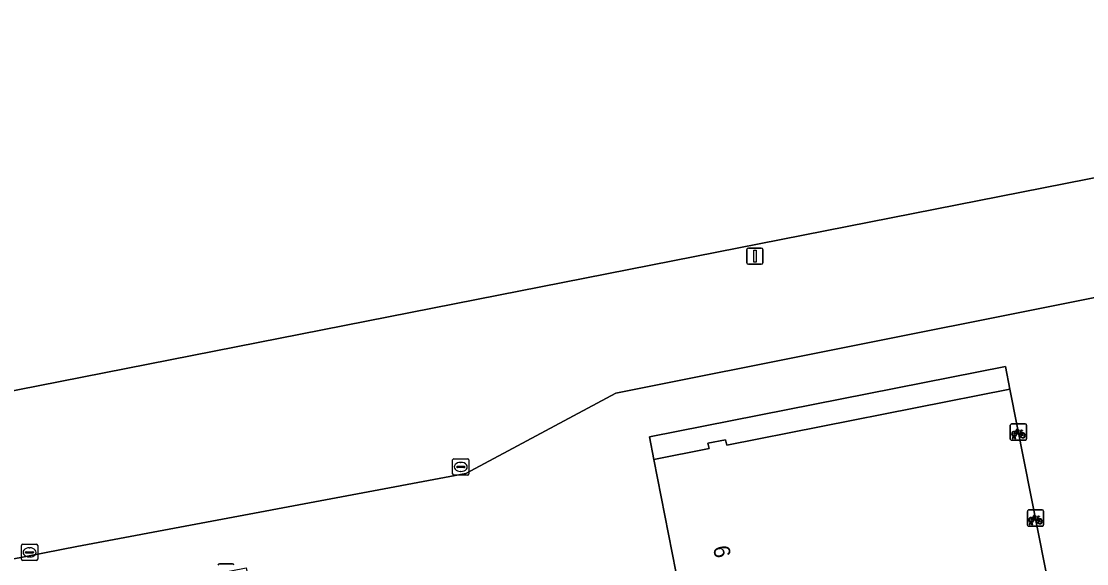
# Model space of a CAD drawing. Extents: x 160203 to 161530, y 379528 to 381797.
# Drawn here: x 160871 to 160936.5, y 380343.8 to 380377.1 of the extents above; entities that cross this region are included whole.
import ezdxf

# ---------------------------------------------------------------- set-up
doc = ezdxf.new("R2010")
doc.units = 0
for name, color, linetype in [('IMGEO_Fietsenrek', 7, 'Continuous'), ('IMGEO_Groenvoorziening', 7, 'Continuous'), ('IMGEO_Kolk', 7, 'Continuous'), ('IMGEO_Lichtmast', 7, 'Continuous'), ('IMGEO_Pand', 7, 'Continuous'), ('IMGEO_Pand_nummerreeks', 7, 'Continuous'), ('IMGEO_Voetpad_open', 7, 'Continuous')]:
    doc.layers.add(name, color=color, linetype=linetype)

msp = doc.modelspace()

# ---------------------------------------------------------------- linework, layer by layer
at = {"layer": 'IMGEO_Fietsenrek'}
for p, q in [((160931.819, 380351.461), (160931.819, 380352.302)), ((160931.819, 380352.302), (160931.819, 380351.461)), ((160931.894, 380352.386), (160932.735, 380352.386)), ((160932.735, 380352.386), (160931.894, 380352.386)), ((160932.819, 380352.311), (160932.819, 380351.47)), ((160932.819, 380351.47), (160932.819, 380352.311)), ((160932.744, 380351.386), (160931.903, 380351.386)), ((160931.903, 380351.386), (160932.744, 380351.386)), ((160931.946, 380351.47), (160931.985, 380351.63)), ((160931.98, 380351.47), (160931.946, 380351.47)), ((160932.015, 380351.618), (160931.98, 380351.47)), ((160932.057, 380351.642), (160932.056, 380351.646)), ((160932.098, 380351.47), (160932.064, 380351.612)), ((160932.088, 380351.653), (160932.089, 380351.646)), ((160932.096, 380351.616), (160932.131, 380351.47)), ((160932.131, 380351.47), (160932.098, 380351.47)), ((160932.506, 380351.935), (160932.542, 380351.84)), ((160932.866, 380346.175), (160932.866, 380347.016)), ((160932.866, 380347.016), (160932.866, 380346.175)), ((160932.941, 380347.1), (160933.782, 380347.1)), ((160933.782, 380347.1), (160932.941, 380347.1)), ((160933.866, 380347.025), (160933.866, 380346.184)), ((160933.866, 380346.184), (160933.866, 380347.025)), ((160932.993, 380346.184), (160933.032, 380346.344)), ((160933.027, 380346.184), (160932.993, 380346.184)), ((160933.062, 380346.332), (160933.027, 380346.184)), ((160933.104, 380346.356), (160933.103, 380346.36)), ((160933.145, 380346.184), (160933.111, 380346.326)), ((160933.135, 380346.367), (160933.136, 380346.36)), ((160933.143, 380346.33), (160933.178, 380346.184)), ((160933.178, 380346.184), (160933.145, 380346.184)), ((160933.553, 380346.649), (160933.589, 380346.554)), ((160933.791, 380346.1), (160932.95, 380346.1)), ((160932.95, 380346.1), (160933.791, 380346.1))]:
    msp.add_line(p, q, dxfattribs=at)
for points in [[(160932.132, 380351.912), (160932.227, 380352.076), (160932.313, 380352.062), (160932.315, 380352.053), (160932.259, 380352.042), (160932.232, 380351.997), (160932.488, 380351.956)], [(160932.488, 380351.956), (160932.513, 380352.005), (160932.507, 380352.009), (160932.484, 380352.013), (160932.472, 380352.02), (160932.471, 380352.023), (160932.473, 380352.028), (160932.568, 380352.013), (160932.57, 380352.003), (160932.56, 380351.99), (160932.548, 380351.984), (160932.534, 380351.99), (160932.506, 380351.935)], [(160932.153, 380351.86), (160932.101, 380351.77), (160932.061, 380351.745), (160932.062, 380351.792), (160932.117, 380351.886)], [(160932.428, 380351.668), (160932.378, 380351.668), (160932.187, 380351.919), (160932.168, 380351.887)], [(160932.475, 380351.931), (160932.218, 380351.972), (160932.201, 380351.943), (160932.368, 380351.723), (160932.475, 380351.931)], [(160932.523, 380351.833), (160932.493, 380351.91), (160932.384, 380351.692), (160932.427, 380351.692)], [(160932.457, 380351.692), (160932.577, 380351.691), (160932.533, 380351.805)], [(160932.553, 380351.812), (160932.608, 380351.667), (160932.458, 380351.667)], [(160933.179, 380346.626), (160933.274, 380346.79), (160933.36, 380346.776), (160933.362, 380346.767), (160933.306, 380346.756), (160933.279, 380346.711), (160933.535, 380346.67)], [(160933.2, 380346.574), (160933.148, 380346.484), (160933.108, 380346.459), (160933.109, 380346.506), (160933.164, 380346.6)], [(160933.475, 380346.382), (160933.425, 380346.382), (160933.234, 380346.633), (160933.215, 380346.601)], [(160933.522, 380346.645), (160933.265, 380346.686), (160933.248, 380346.657), (160933.415, 380346.437), (160933.522, 380346.645)], [(160933.57, 380346.547), (160933.54, 380346.624), (160933.431, 380346.406), (160933.474, 380346.406)], [(160933.504, 380346.406), (160933.624, 380346.405), (160933.58, 380346.519)], [(160933.6, 380346.526), (160933.655, 380346.381), (160933.505, 380346.381)], [(160933.535, 380346.67), (160933.56, 380346.719), (160933.554, 380346.723), (160933.531, 380346.727), (160933.519, 380346.734), (160933.518, 380346.737), (160933.52, 380346.742), (160933.615, 380346.727), (160933.617, 380346.717), (160933.607, 380346.704), (160933.595, 380346.698), (160933.581, 380346.704), (160933.553, 380346.649)]]:
    msp.add_lwpolyline(points, dxfattribs=at)
for centre, radius, start, end in [((160931.897, 380352.308), 0.0779, 92.4484, 184.28452), ((160931.897, 380352.308), 0.0779, 92.4484, 184.28452), ((160932.741, 380352.308), 0.0779, 2.4484, 94.28452), ((160932.741, 380352.308), 0.0779, 2.4484, 94.28452), ((160931.897, 380351.464), 0.0779, 182.4484, 274.28452), ((160931.897, 380351.464), 0.0779, 182.4484, 274.28452), ((160932.059, 380351.771), 0.159, 62.67661, 242.13685), ((160932.059, 380351.771), 0.129, 63.31916, 238.90302), ((160932.039, 380351.642), 0.0499, 12.8025, 158.69338), ((160932.059, 380351.771), 0.159, 253.99666, 271.78671), ((160932.039, 380351.642), 0.0174, 12.8025, 163.45023), ((160932.059, 380351.771), 0.129, 253.41502, 269.02044), ((160932.059, 380351.771), 0.129, 283.60429, 43.43025), ((160932.059, 380351.771), 0.159, 283.5766, 46.60424), ((160932.586, 380351.687), 0.159, 113.3408, 178.32165), ((160932.586, 380351.687), 0.159, 187.0065, 105.77075), ((160932.586, 380351.687), 0.129, 113.92302, 177.95563), ((160932.586, 380351.687), 0.129, 188.67146, 104.58832), ((160932.741, 380351.464), 0.0779, 272.4484, 4.28452), ((160932.741, 380351.464), 0.0779, 272.4484, 4.28452), ((160932.944, 380347.022), 0.0779, 92.4484, 184.28452), ((160932.944, 380347.022), 0.0779, 92.4484, 184.28452), ((160933.788, 380347.022), 0.0779, 2.4484, 94.28452), ((160933.788, 380347.022), 0.0779, 2.4484, 94.28452), ((160932.944, 380346.178), 0.0779, 182.4484, 274.28452), ((160932.944, 380346.178), 0.0779, 182.4484, 274.28452), ((160933.106, 380346.485), 0.159, 62.67661, 242.13685), ((160933.106, 380346.485), 0.129, 63.31916, 238.90302), ((160933.086, 380346.356), 0.0499, 12.8025, 158.69338), ((160933.106, 380346.485), 0.159, 253.99666, 271.78671), ((160933.086, 380346.356), 0.0174, 12.8025, 163.45023), ((160933.106, 380346.485), 0.129, 253.41502, 269.02044), ((160933.106, 380346.485), 0.129, 283.60429, 43.43025), ((160933.106, 380346.485), 0.159, 283.5766, 46.60424), ((160933.633, 380346.401), 0.159, 113.3408, 178.32165), ((160933.633, 380346.401), 0.159, 187.0065, 105.77075), ((160933.633, 380346.401), 0.129, 113.92302, 177.95563), ((160933.633, 380346.401), 0.129, 188.67146, 104.58832), ((160933.788, 380346.178), 0.0779, 272.4484, 4.28452), ((160933.788, 380346.178), 0.0779, 272.4484, 4.28452)]:
    msp.add_arc(centre, radius, start, end, dxfattribs=at)
at = {"layer": 'IMGEO_Groenvoorziening'}
for points in [[(160947.345, 380500), (160946.869, 380502.452), (160944.615, 380512.001), (160902.101, 380503.8), (160879.901, 380499.518), (160834.638, 380490.788), (160834.2, 380490.611), (160833.852, 380490.316), (160833.56, 380489.783), (160833.499, 380489.33), (160863.045, 380342.63), (160874.441, 380344.866), (160898.366, 380349.337), (160907.573, 380354.284), (160962.354, 380365.201), (160969.347, 380366.563), (160972.472, 380371.216), (160971.163, 380377.952), (160966.73, 380400.144), (160956.686, 380451.885)], [(160966.11, 380373.245), (160953.284, 380437.896), (160852.978, 380417.957), (160865.398, 380353.411)], [(160953.284, 380437.896), (160966.11, 380373.245), (160865.398, 380353.411), (160852.978, 380417.957)]]:
    msp.add_lwpolyline(points, close=True, dxfattribs=at)
at = {"layer": 'IMGEO_Kolk'}
for p, q in [((160897.545, 380349.32), (160897.545, 380350.172)), ((160897.62, 380350.246), (160898.472, 380350.246)), ((160898.546, 380350.172), (160898.546, 380349.32)), ((160897.804, 380349.74), (160897.804, 380349.752)), ((160898.242, 380349.703), (160897.844, 380349.703)), ((160897.847, 380349.789), (160898.245, 380349.789)), ((160898.056, 380349.466), (160898.031, 380349.466)), ((160898.033, 380350.026), (160898.058, 380350.026)), ((160898.288, 380349.752), (160898.288, 380349.74)), ((160898.472, 380349.246), (160897.62, 380349.246)), ((160871.042, 380344.071), (160871.042, 380344.923)), ((160871.117, 380344.997), (160871.969, 380344.997)), ((160872.043, 380344.923), (160872.043, 380344.071)), ((160871.301, 380344.491), (160871.301, 380344.503)), ((160871.739, 380344.454), (160871.341, 380344.454)), ((160871.344, 380344.54), (160871.742, 380344.54)), ((160871.553, 380344.217), (160871.528, 380344.217)), ((160871.53, 380344.777), (160871.555, 380344.777)), ((160871.785, 380344.503), (160871.785, 380344.491)), ((160871.969, 380343.997), (160871.117, 380343.997))]:
    msp.add_line(p, q, dxfattribs=at)
for points in [[(160897.545, 380349.32), (160897.545, 380350.172)], [(160897.62, 380350.246), (160898.472, 380350.246)], [(160898.546, 380350.172), (160898.546, 380349.32)], [(160898.472, 380349.246), (160897.62, 380349.246)], [(160871.042, 380344.071), (160871.042, 380344.923)], [(160871.117, 380344.997), (160871.969, 380344.997)], [(160872.043, 380344.923), (160872.043, 380344.071)], [(160871.969, 380343.997), (160871.117, 380343.997)]]:
    msp.add_lwpolyline(points, dxfattribs=at)
for centre, radius, start, end in [((160897.622, 380350.17), 0.0765, 91.55205, 178.44795), ((160897.622, 380350.17), 0.0765, 91.55205, 178.44795), ((160898.47, 380350.17), 0.0765, 1.55205, 88.44795), ((160898.47, 380350.17), 0.0765, 1.55205, 88.44795), ((160897.844, 380349.749), 0.0403, 85.87752, 175.75265), ((160897.841, 380349.739), 0.0366, 178.93798, 274.71019), ((160898.245, 380349.746), 0.043, 264.86636, 352.45326), ((160898.249, 380349.751), 0.0386, 1.73085, 96.63898), ((160897.622, 380349.322), 0.0765, 181.55205, 268.44795), ((160897.622, 380349.322), 0.0765, 181.55205, 268.44795), ((160898.47, 380349.322), 0.0765, 271.55205, 358.44795), ((160898.47, 380349.322), 0.0765, 271.55205, 358.44795), ((160871.119, 380344.921), 0.0765, 91.55205, 178.44795), ((160871.119, 380344.921), 0.0765, 91.55205, 178.44795), ((160871.967, 380344.921), 0.0765, 1.55205, 88.44795), ((160871.967, 380344.921), 0.0765, 1.55205, 88.44795), ((160871.341, 380344.5), 0.0403, 85.87752, 175.75265), ((160871.338, 380344.49), 0.0366, 178.93798, 274.71019), ((160871.742, 380344.497), 0.043, 264.86636, 352.45326), ((160871.746, 380344.502), 0.0386, 1.73085, 96.63898), ((160871.119, 380344.073), 0.0765, 181.55205, 268.44795), ((160871.119, 380344.073), 0.0765, 181.55205, 268.44795), ((160871.967, 380344.073), 0.0765, 271.55205, 358.44795), ((160871.967, 380344.073), 0.0765, 271.55205, 358.44795)]:
    msp.add_arc(centre, radius, start, end, dxfattribs=at)
for centre, major_axis, ratio, start_param, end_param in [((160898.032, 380349.746), (-0.387, 0.002), 0.722429, 4.712389, 7.853982), ((160898.057, 380349.746), (-0.39, 0.002), 0.717154, 1.570796, 4.712389), ((160871.529, 380344.497), (-0.387, 0.002), 0.722429, 4.712389, 7.853982), ((160871.554, 380344.497), (-0.39, 0.002), 0.717154, 1.570796, 4.712389)]:
    msp.add_ellipse(centre, major_axis=major_axis, ratio=ratio, start_param=start_param, end_param=end_param, dxfattribs=at)
at = {"layer": 'IMGEO_Lichtmast'}
for p, q in [((160915.727, 380363.192), (160916.517, 380363.192)), ((160916.517, 380363.192), (160915.727, 380363.192)), ((160915.627, 380362.292), (160915.627, 380363.092)), ((160915.627, 380363.092), (160915.627, 380362.292)), ((160916.617, 380363.092), (160916.617, 380362.292)), ((160916.617, 380362.292), (160916.617, 380363.092)), ((160916.517, 380362.192), (160915.727, 380362.192)), ((160915.727, 380362.192), (160916.517, 380362.192)), ((160883.218, 380343.803), (160884.008, 380343.803)), ((160884.008, 380343.803), (160883.218, 380343.803))]:
    msp.add_line(p, q, dxfattribs=at)
msp.add_lwpolyline([(160916.047, 380363.067), (160916.197, 380363.067), (160916.197, 380362.317), (160916.047, 380362.317), (160916.047, 380363.067)], dxfattribs=at)
for centre, start, end in [((160915.727, 380363.092), 90, 180), ((160915.727, 380363.092), 90, 180), ((160916.517, 380363.092), 0, 90), ((160916.517, 380363.092), 360, 90), ((160915.727, 380362.292), 180, 270), ((160915.727, 380362.292), 180, 270), ((160916.517, 380362.292), 270, 0), ((160916.517, 380362.292), 270, 0), ((160883.218, 380343.703), 90, 180), ((160883.218, 380343.703), 90, 180), ((160884.008, 380343.703), 0, 90), ((160884.008, 380343.703), 360, 90)]:
    msp.add_arc(centre, 0.1, start, end, dxfattribs=at)
at = {"layer": 'IMGEO_Pand'}
msp.add_lwpolyline([(160927.424, 380335.503), (160935.257, 380337.055), (160931.797, 380354.522), (160914.391, 380351.074), (160914.323, 380351.416), (160913.239, 380351.201), (160913.302, 380350.883), (160909.903, 380350.209), (160911.948, 380339.889), (160912.341, 380337.903), (160912.634, 380336.424), (160912.885, 380336.474), (160912.592, 380337.953), (160924.986, 380340.408), (160925.433, 380338.153), (160925.759, 380336.506), (160926.013, 380335.224)], close=True, dxfattribs=at)
at = {"layer": 'IMGEO_Voetpad_open'}
for points in [[(160962.354, 380365.201), (160907.573, 380354.284), (160898.366, 380349.337), (160874.441, 380344.866), (160863.045, 380342.63), (160862.461, 380342.515), (160863.415, 380337.765), (160867.026, 380338.466), (160870.751, 380339.189), (160870.472, 380340.734), (160871.69, 380340.974), (160884.859, 380343.545), (160887.626, 380328.963), (160897.767, 380330.929), (160898.212, 380328.588), (160898.548, 380326.947), (160983.227, 380343.654)], [(160911.948, 380339.889), (160909.903, 380350.209), (160909.653, 380351.596), (160931.519, 380355.924), (160931.797, 380354.522), (160935.257, 380337.055)]]:
    msp.add_lwpolyline(points, dxfattribs=at)
msp.add_lwpolyline([(160931.519, 380355.924), (160909.653, 380351.596), (160909.903, 380350.209), (160913.302, 380350.883), (160913.239, 380351.201), (160914.323, 380351.416), (160914.391, 380351.074), (160931.797, 380354.522)], close=True, dxfattribs=at)

# ---------------------------------------------------------------- texts
at = {"layer": 'IMGEO_Pand_nummerreeks'}
msp.add_text('6', height=1, rotation=281.20598, dxfattribs=at).set_placement((160913.54, 380344.816))

doc.saveas('drawing.dxf')
